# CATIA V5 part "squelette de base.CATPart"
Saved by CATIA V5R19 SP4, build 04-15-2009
Part number: squelette de base
Property "profondeur_treuil": 500 mm
Bounding box of the stored display mesh (mm): x -500 to 500, y 0 to 1200, z -180 to 1800
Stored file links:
  G:\EU_thinkMotion\CFAO_2010\MMS_groupe1\MMS_groupe1\OK\rragonneau\rragonneau\squelette de base.CATPart
  D:\Documents\Scolaire\MM2\CFAO\Brevet\MODELE CATIA\Squelette\Deambulateur.CATProduct
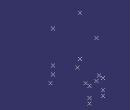
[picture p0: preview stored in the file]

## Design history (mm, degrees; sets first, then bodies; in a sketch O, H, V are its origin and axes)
Parameters
  longueur_bras = 350 mm
  hauteur_deamb = 1800 mm
  profondeur_deamb = 1200 mm
  hauteur_siege = 400 mm
  largeur_siege = 500 mm
  profondeur_treuil = 1000 mm
  diam_roue = 200 mm
  largeur_deamb = 1000 mm
  hauteur_support_main = 900 mm
External parameters (linked from other documents)
  External.largeur_deamb = 1000 mm
  `External.diam_moyeu_ext / epaisseur_bras&montant` = 60 mm
  External.diam_jante = 500 mm
  External.epaisseur_pneu = 60 mm
Set1
  Point1: (500 {= largeur_deamb/2}, 0, 0)
  Point2: (500 {= largeur_deamb/2}, 100, 335.4102 {= sqrt(longueur_bras *longueur_bras -100mm*100mm)})
  Point3: (500 {= largeur_deamb/2}, 100, 1800 {= hauteur_deamb})
  Point4: (-500 {= -largeur_deamb/2}, 100, 1800 {= hauteur_deamb})
  Point5: (-500 {= -largeur_deamb/2}, 100, 335.4102 {= sqrt(longueur_bras *longueur_bras -100mm*100mm)})
  Point6: (-500 {= -largeur_deamb/2}, 0, 0)
  Point7: (0, 1200 {= profondeur_deamb}, 1800 {= hauteur_deamb})
  Point8: (0, 1200 {= profondeur_deamb}, 415 {= hauteur_siege +`External.diam_moyeu_ext / epaisseur_bras&montant` /4})
  Point9: (-250 {= -largeur_siege /2}, 1200 {= profondeur_deamb}, 400 {= hauteur_siege})
  Point10: (250 {= largeur_siege /2}, 1200 {= profondeur_deamb}, 400 {= hauteur_siege})
  Point11: (-250 {= -largeur_siege /2}, 1050 {= profondeur_deamb -150mm}, 400 {= hauteur_siege})
  Point12: (250 {= largeur_siege/2}, 1050 {= profondeur_deamb -150mm}, 400 {= hauteur_siege})
  Point13: (250 {= largeur_siege /2}, 1200 {= profondeur_deamb}, 0)
  Point14: (-250 {= -largeur_siege /2}, 1200 {= profondeur_deamb}, 0)
  Point15: (250 {= largeur_siege /2}, 1200 {= profondeur_deamb}, -180 {= -External.diam_jante/2 -External.epaisseur_pneu/2+ diam_roue/2})
  Point16: (-250 {= -largeur_siege /2}, 1200 {= profondeur_deamb}, -180 {= -External.diam_jante /2-External.epaisseur_pneu /2+diam_roue /2})
  Point17: (500 {= largeur_deamb /2}, 100, 620 {= hauteur_support_main -External.diam_jante /2-External.epaisseur_pneu /2})
Body1 (main body)
Relations
  Point15.Z = -`Paramètres externes\diam_jante` /2-`Paramètres externes\epaisseur_pneu` /2- (deactivated)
